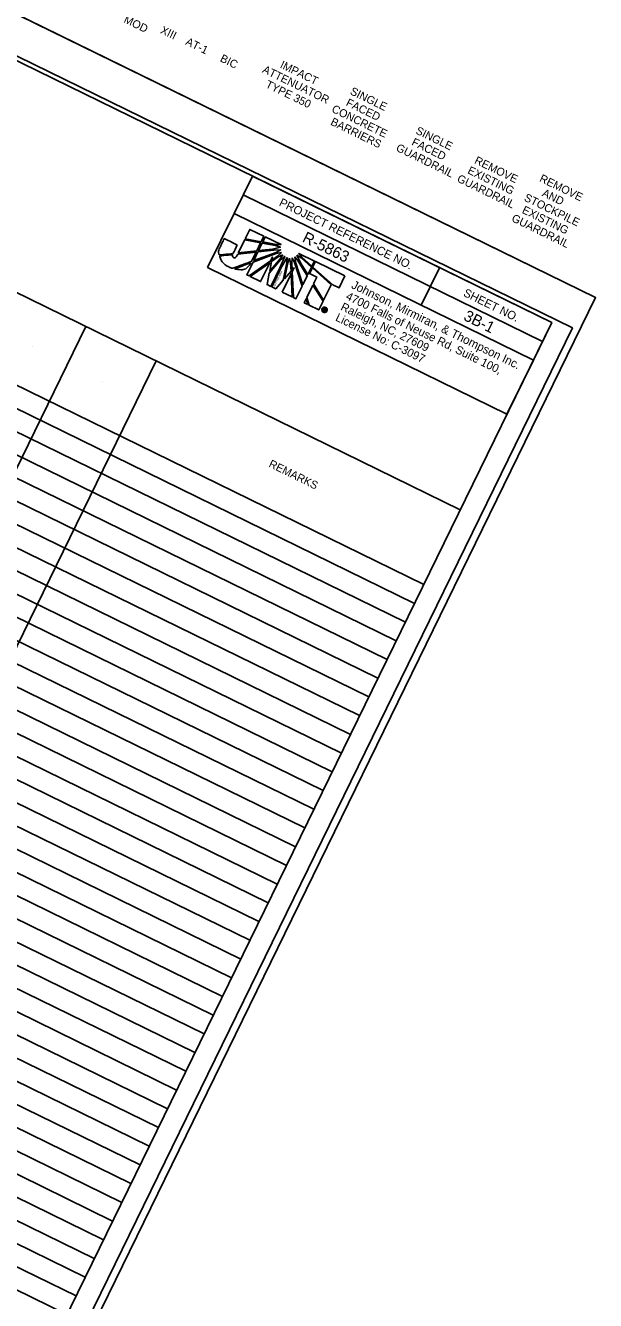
# Model space of a CAD drawing. Extents: x 1524707 to 1527186, y 631886 to 634602.
# Drawn here: x 1526844 to 1527186, y 633261 to 634025 of the extents above; entities that cross this region are included whole.
import ezdxf

# ---------------------------------------------------------------- set-up
doc = ezdxf.new("R2010")
doc.units = 0
for name, color, linetype in [('Sheet Cutting Line CELL', 7, 'Continuous'), ('Sheet Data Field CELL', 7, 'Continuous'), ('Sheet Pipe Summary Grid CELL', 7, 'Continuous'), ('Sheet Plot Border Inside CELL', 7, 'Continuous'), ('Sheet Plot Border Outside CELL', 7, 'Continuous'), ('Sheet Summary Guardrail CELL', 7, 'Continuous')]:
    doc.layers.add(name, color=color, linetype=linetype)

msp = doc.modelspace()

# ---------------------------------------------------------------- linework, layer by layer
at = {"layer": 'Sheet Cutting Line CELL'}
msp.add_line((1527186.47, 633862.17), (1525673.71, 634602.03), dxfattribs=at)
at = {"layer": 'Sheet Pipe Summary Grid CELL'}
for p, q in [((1526978.93, 633903.02), (1526976.21, 633897.44)), ((1526987.35, 633898.92), (1526978.93, 633903.02)), ((1526975.9, 633896.8), (1526972.07, 633888.96)), ((1526985.46, 633895.06), (1526975.9, 633896.8)), ((1526976.21, 633897.44), (1526985.76, 633895.67)), ((1526983.08, 633890.19), (1526985.46, 633895.06)), ((1526986.45, 633894.87), (1526984.23, 633890.32)), ((1526985.76, 633895.67), (1526987.35, 633898.92)), ((1526994.45, 633893.37), (1526986.45, 633894.87)), ((1526988.24, 633898.53), (1526986.77, 633895.52)), ((1526986.77, 633895.52), (1526994.77, 633894.02)), ((1526997.71, 633893.92), (1526988.24, 633898.53)), ((1526972.07, 633888.96), (1526983.08, 633890.19)), ((1526994.82, 633888.6), (1526980.88, 633883.44)), ((1526983.87, 633889.58), (1526981.31, 633884.33)), ((1526981.31, 633884.33), (1526994.69, 633889.24)), ((1526993.42, 633890.66), (1526983.87, 633889.58)), ((1526984.23, 633890.32), (1526992.5, 633891.23)), ((1526992.23, 633884.69), (1526995.56, 633887.04)), ((1526992.5, 633891.23), (1526997.36, 633892.36)), ((1526997.42, 633890.72), (1526993.42, 633890.66)), ((1526997.36, 633892.36), (1526994.45, 633893.37)), ((1526994.69, 633889.24), (1526997.42, 633890.72)), ((1526994.77, 633894.02), (1526997.71, 633893.92)), ((1526997.9, 633889.23), (1526994.82, 633888.6)), ((1526995.56, 633887.04), (1526997.9, 633889.23)), ((1526998.74, 633887.89), (1526996.03, 633886.57)), ((1526997.24, 633885.41), (1526998.74, 633887.89)), ((1527007.28, 633887.53), (1527009.39, 633882.92)), ((1527009.71, 633885.93), (1527007.28, 633887.53)), ((1527017.74, 633884.09), (1527008.43, 633888.69)), ((1527008.43, 633888.69), (1527010.25, 633886.42)), ((1526980.88, 633883.44), (1526977.15, 633875.81)), ((1526978.54, 633875.13), (1526991.47, 633884.2)), ((1526990.89, 633883), (1526979.19, 633874.81)), ((1526985.47, 633871.75), (1526990.89, 633883)), ((1526997.48, 633884.71), (1526990.67, 633876.78)), ((1526990.96, 633878.08), (1526997.24, 633885.41)), ((1526992.08, 633883.79), (1526990.96, 633878.08)), ((1526991.47, 633884.2), (1526992.56, 633886.42)), ((1526991.6, 633868.81), (1526997.07, 633880.03)), ((1526996.03, 633886.57), (1526992.08, 633883.79)), ((1526997.67, 633879.74), (1526992.19, 633868.52)), ((1526992.56, 633886.42), (1526992.23, 633884.69)), ((1526997.07, 633880.03), (1526999.95, 633886.84)), ((1526999.95, 633886.84), (1526997.48, 633884.71)), ((1527001.34, 633886.16), (1526997.67, 633879.74)), ((1526999.04, 633872.52), (1527001.13, 633882.93)), ((1527001.83, 633883.05), (1526999.86, 633873.49)), ((1527001.13, 633882.93), (1527001.34, 633886.16)), ((1527002.86, 633885.88), (1527001.83, 633883.05)), ((1527003.45, 633882.95), (1527002.86, 633885.88)), ((1527003.7, 633877.95), (1527003.45, 633882.95)), ((1527004.42, 633886.05), (1527004.14, 633882.85)), ((1527004.14, 633882.85), (1527004.31, 633878.63)), ((1527004.31, 633878.63), (1527005.55, 633880.08)), ((1527005.55, 633880.08), (1527004.35, 633877.63)), ((1527005.82, 633883.24), (1527004.42, 633886.05)), ((1527010.3, 633868.99), (1527005.82, 633883.24)), ((1527005.9, 633886.58), (1527006.4, 633883.47)), ((1527008.36, 633883.37), (1527005.9, 633886.58)), ((1527006.4, 633883.47), (1527010.72, 633869.86)), ((1527013.35, 633875.25), (1527008.36, 633883.37)), ((1527009.39, 633882.92), (1527013.72, 633876)), ((1527015.95, 633880.43), (1527009.71, 633885.93)), ((1527010.25, 633886.42), (1527016.26, 633881.07)), ((1527013.72, 633876), (1527015.95, 633880.43)), ((1527016.51, 633879.91), (1527014.85, 633876.53)), ((1527016.26, 633881.07), (1527017.74, 633884.09)), ((1527016.53, 633879.97), (1527016.51, 633879.91)), ((1527027.75, 633869.89), (1527016.53, 633879.97)), ((1527016.82, 633880.57), (1527016.78, 633880.47)), ((1527016.78, 633880.47), (1527028.8, 633869.77)), ((1527018.41, 633883.82), (1527016.82, 633880.57)), ((1527036.1, 633875.19), (1527018.41, 633883.82)), ((1526977.15, 633875.81), (1526978.54, 633875.13)), ((1526979.19, 633874.81), (1526985.47, 633871.75)), ((1526990.67, 633876.78), (1526989.29, 633869.94)), ((1526994.53, 633867.38), (1526999.04, 633872.52)), ((1527003.77, 633876.42), (1526998.43, 633865.48)), ((1526999.86, 633873.49), (1527003.7, 633877.95)), ((1527004.45, 633862.54), (1527003.77, 633876.42)), ((1527004.35, 633877.63), (1527005.13, 633862.16)), ((1527010.72, 633869.86), (1527013.35, 633875.25)), ((1527014.85, 633876.53), (1527019.17, 633874.42)), ((1527019.17, 633874.42), (1527017.2, 633870.38)), ((1527032.56, 633867.94), (1527036.1, 633875.19)), ((1526989.29, 633869.94), (1526991.6, 633868.81)), ((1526992.19, 633868.52), (1526994.53, 633867.38)), ((1526998.43, 633865.48), (1527004.45, 633862.54)), ((1527006.61, 633861.43), (1527010.3, 633868.99)), ((1527016.86, 633869.69), (1527013.19, 633862.16)), ((1527022.9, 633859.95), (1527016.86, 633869.69)), ((1527017.2, 633870.38), (1527023.22, 633860.6)), ((1527023.22, 633860.6), (1527027.75, 633869.89)), ((1527028.8, 633869.77), (1527032.56, 633867.94)), ((1527005.13, 633862.16), (1527006.61, 633861.43)), ((1527012.79, 633861.34), (1527011.64, 633858.98)), ((1527011.64, 633858.98), (1527013.82, 633857.92)), ((1527013.82, 633857.92), (1527012.79, 633861.34)), ((1527013.19, 633862.16), (1527014.65, 633857.51)), ((1527014.65, 633857.51), (1527020.36, 633854.73)), ((1527020.36, 633854.73), (1527022.9, 633859.95)), ((1527022.96, 633854.44), (1527023.59, 633855.73)), ((1527023.25, 633854.3), (1527022.96, 633854.44)), ((1527023.24, 633853.68), (1527023.1, 633853.4)), ((1527023.1, 633853.4), (1527023.24, 633853.68)), ((1527023.12, 633853.4), (1527023.1, 633853.4)), ((1527023.24, 633853.68), (1527023.25, 633853.68)), ((1527023.5, 633854.8), (1527023.25, 633854.3)), ((1527023.73, 633854.69), (1527023.5, 633854.8)), ((1527023.59, 633855.73), (1527024.11, 633855.47)), ((1527023.76, 633855.34), (1527023.61, 633855.04)), ((1527023.61, 633855.04), (1527023.84, 633854.92)), ((1527023.84, 633854.92), (1527023.73, 633854.69)), ((1527023.73, 633854.69), (1527023.84, 633854.92)), ((1527023.74, 633854.68), (1527023.73, 633854.69)), ((1527023.99, 633855.23), (1527023.76, 633855.34)), ((1527023.84, 633854.92), (1527023.86, 633854.92)), ((1527024.11, 633855.47), (1527023.99, 633855.23)), ((1527023.99, 633855.23), (1527024.11, 633855.47)), ((1527024.03, 633855.21), (1527023.99, 633855.23)), ((1527024.11, 633855.47), (1527024.19, 633855.43)), ((1527024.48, 633856.23), (1527024.35, 633855.96)), ((1527024.35, 633855.96), (1527024.48, 633856.23))]:
    msp.add_line(p, q, dxfattribs=at)
msp.add_lwpolyline([(1526953.65, 633880.14), (1527133.34, 633792.25), (1527149.2, 633824.68), (1526969.5, 633912.57)], close=True, dxfattribs=at)
for points in [[(1526976.21, 633897.44), (1526985.76, 633895.67), (1526987.35, 633898.92), (1526978.93, 633903.02), (1526976.21, 633897.44)], [(1526972.07, 633888.96), (1526983.08, 633890.19), (1526985.46, 633895.06), (1526975.9, 633896.8), (1526972.07, 633888.96)], [(1526986.45, 633894.87), (1526984.23, 633890.32), (1526992.5, 633891.23), (1526997.36, 633892.36), (1526994.45, 633893.37), (1526986.45, 633894.87)], [(1526994.77, 633894.02), (1526997.71, 633893.92), (1526988.24, 633898.53), (1526986.77, 633895.52), (1526994.77, 633894.02)], [(1526997.9, 633889.23), (1526994.82, 633888.6), (1526980.88, 633883.44), (1526977.15, 633875.81), (1526978.54, 633875.13), (1526991.47, 633884.2), (1526992.56, 633886.42), (1526992.23, 633884.69), (1526995.56, 633887.04), (1526997.9, 633889.23)], [(1526983.87, 633889.58), (1526981.31, 633884.33), (1526994.69, 633889.24), (1526997.42, 633890.72), (1526993.42, 633890.66), (1526983.87, 633889.58)], [(1526998.74, 633887.89), (1526996.03, 633886.57), (1526992.08, 633883.79), (1526990.96, 633878.08), (1526997.24, 633885.41), (1526998.74, 633887.89)], [(1527007.28, 633887.53), (1527009.39, 633882.92), (1527013.72, 633876), (1527015.95, 633880.43), (1527009.71, 633885.93), (1527007.28, 633887.53)], [(1527010.25, 633886.42), (1527016.26, 633881.07), (1527017.74, 633884.09), (1527008.43, 633888.69), (1527010.25, 633886.42)], [(1526979.19, 633874.81), (1526985.47, 633871.75), (1526990.89, 633883), (1526979.19, 633874.81)], [(1526997.48, 633884.71), (1526990.67, 633876.78), (1526989.29, 633869.94), (1526991.6, 633868.81), (1526997.07, 633880.03), (1526999.95, 633886.84), (1526997.48, 633884.71)], [(1527001.34, 633886.16), (1526997.67, 633879.74), (1526992.19, 633868.52), (1526994.53, 633867.38), (1526999.04, 633872.52), (1527001.13, 633882.93), (1527001.34, 633886.16)], [(1527002.86, 633885.88), (1527001.83, 633883.05), (1526999.86, 633873.49), (1527003.7, 633877.95), (1527003.45, 633882.95), (1527002.86, 633885.88)], [(1527004.42, 633886.05), (1527004.14, 633882.85), (1527004.31, 633878.63), (1527005.55, 633880.08), (1527004.35, 633877.63), (1527005.13, 633862.16), (1527006.61, 633861.43), (1527010.3, 633868.99), (1527005.82, 633883.24), (1527004.42, 633886.05)], [(1527005.9, 633886.58), (1527006.4, 633883.47), (1527010.72, 633869.86), (1527013.35, 633875.25), (1527008.36, 633883.37), (1527005.9, 633886.58)], [(1527016.53, 633879.97), (1527016.51, 633879.91), (1527014.85, 633876.53), (1527019.17, 633874.42), (1527017.2, 633870.38), (1527023.22, 633860.6), (1527027.75, 633869.89), (1527016.53, 633879.97)], [(1527036.1, 633875.19), (1527018.41, 633883.82), (1527016.82, 633880.57), (1527016.78, 633880.47), (1527028.8, 633869.77), (1527032.56, 633867.94), (1527036.1, 633875.19)], [(1526998.43, 633865.48), (1527004.45, 633862.54), (1527003.77, 633876.42), (1526998.43, 633865.48)], [(1527016.86, 633869.69), (1527013.19, 633862.16), (1527014.65, 633857.51), (1527020.36, 633854.73), (1527022.9, 633859.95), (1527016.86, 633869.69), (1527016.86, 633869.69)], [(1527011.64, 633858.98), (1527011.64, 633858.98), (1527013.82, 633857.92), (1527012.79, 633861.34), (1527011.64, 633858.98)], [(1527024.2, 633854.21), (1527024.16, 633854.14), (1527024.15, 633854.09), (1527024.13, 633854.05), (1527024.09, 633853.89), (1527023.82, 633854.02)]]:
    msp.add_lwpolyline(points, dxfattribs=at)
for points, degree in [([(1526971.42, 633893.75), (1526971.42, 633893.75), (1526963.63, 633897.55), (1526963.63, 633897.55), (1526963.63, 633897.55), (1526961.25, 633892.68), (1526961.25, 633892.68), (1526961.25, 633892.68), (1526961, 633892.16), (1526961, 633892.16), (1526960.25, 633890.64), (1526960.16, 633889.18), (1526960.56, 633887.74), (1526960.56, 633887.74), (1526968.86, 633888.5), (1526968.9, 633888.6), (1526968.9, 633888.6), (1526971.42, 633893.75), (1526971.42, 633893.75)], 3), ([(1526969.2, 633886.15), (1526968.7, 633886.39), (1526968.41, 633886.88), (1526968.68, 633887.9), (1526968.68, 633887.9), (1526960.82, 633887.11), (1526960.82, 633887.11), (1526961.73, 633884.25), (1526964.13, 633881.63), (1526966.64, 633880.4), (1526967.29, 633880.09), (1526967.82, 633879.9), (1526968.58, 633879.7), (1526968.58, 633879.7), (1526979.98, 633883.83), (1526979.98, 633883.83), (1526979.98, 633883.83), (1526982.75, 633889.49), (1526982.75, 633889.49), (1526982.75, 633889.49), (1526971.72, 633888.25), (1526971.72, 633888.25), (1526970.69, 633886.13), (1526969.9, 633885.81), (1526969.2, 633886.15)], 3), ([(1526969.2, 633886.15), (1526968.7, 633886.39), (1526968.41, 633886.88), (1526968.68, 633887.9), (1526968.68, 633887.9), (1526960.82, 633887.11), (1526960.82, 633887.11), (1526961.73, 633884.25), (1526964.13, 633881.63), (1526966.64, 633880.4), (1526967.29, 633880.09), (1526967.82, 633879.9), (1526968.58, 633879.7), (1526968.58, 633879.7), (1526979.98, 633883.83), (1526979.98, 633883.83), (1526979.98, 633883.83), (1526982.75, 633889.49), (1526982.75, 633889.49), (1526982.75, 633889.49), (1526971.72, 633888.25), (1526971.72, 633888.25), (1526970.69, 633886.13), (1526969.9, 633885.81), (1526969.2, 633886.15)], 3), ([(1526979.55, 633882.94), (1526979.55, 633882.94), (1526969.7, 633879.38), (1526969.7, 633879.38), (1526973.29, 633878.6), (1526977.52, 633879.17), (1526979.55, 633882.94)], 3), ([(1527023.1, 633853.4), (1527022.72, 633853.59), (1527022.45, 633853.9), (1527022.3, 633854.31), (1527022.15, 633854.72), (1527022.18, 633855.13), (1527022.37, 633855.52), (1527022.57, 633855.92), (1527022.87, 633856.19), (1527023.28, 633856.31), (1527023.69, 633856.44), (1527024.09, 633856.43), (1527024.48, 633856.23)], 3), ([(1527024.35, 633855.96), (1527024.04, 633856.12), (1527023.72, 633856.14), (1527023.39, 633856.04), (1527023.06, 633855.93), (1527022.81, 633855.7), (1527022.65, 633855.39), (1527022.5, 633855.07), (1527022.48, 633854.73), (1527022.59, 633854.4), (1527022.71, 633854.07), (1527022.92, 633853.84), (1527023.24, 633853.68)], 3), ([(1527025.24, 633854.13), (1527025.04, 633853.73), (1527024.74, 633853.46), (1527024.33, 633853.31), (1527023.92, 633853.18), (1527023.51, 633853.2), (1527023.12, 633853.4)], 3), ([(1527023.25, 633853.68), (1527023.57, 633853.52), (1527023.89, 633853.5), (1527024.22, 633853.61), (1527024.55, 633853.72), (1527024.8, 633853.95), (1527024.96, 633854.26), (1527025.11, 633854.58), (1527025.13, 633854.92), (1527025.02, 633855.25), (1527024.9, 633855.57), (1527024.68, 633855.8), (1527024.35, 633855.96)], 3), ([(1527023.94, 633854.53), (1527023.92, 633854.57), (1527023.86, 633854.62), (1527023.74, 633854.68)], 2), ([(1527023.82, 633854.02), (1527023.82, 633854.11), (1527023.83, 633854.19), (1527023.88, 633854.28), (1527023.94, 633854.4), (1527023.96, 633854.47), (1527023.94, 633854.53)], 3), ([(1527023.86, 633854.92), (1527024.04, 633854.82), (1527024.17, 633854.84), (1527024.22, 633854.94), (1527024.26, 633855.04), (1527024.2, 633855.12), (1527024.03, 633855.21)], 3), ([(1527024.19, 633855.43), (1527024.52, 633855.27), (1527024.62, 633855.06), (1527024.5, 633854.81), (1527024.44, 633854.69), (1527024.35, 633854.62), (1527024.21, 633854.6)], 3), ([(1527024.21, 633854.6), (1527024.27, 633854.51), (1527024.26, 633854.38), (1527024.2, 633854.21)], 2), ([(1527024.48, 633856.23), (1527024.88, 633856.04), (1527025.15, 633855.73), (1527025.3, 633855.33), (1527025.46, 633854.93), (1527025.43, 633854.52), (1527025.24, 633854.13)], 3)]:
    msp.add_open_spline(points, degree=degree, dxfattribs=at)
at = {"layer": 'Sheet Plot Border Inside CELL'}
msp.add_lwpolyline([(1525211.97, 633628.34), (1526709.01, 632896.16), (1527172.57, 633843.98), (1525675.52, 634576.15)], close=True, dxfattribs=at)
at = {"layer": 'Sheet Plot Border Outside CELL'}
msp.add_lwpolyline([(1525190.43, 633613.88), (1526703.19, 632874.02), (1527186.47, 633862.17), (1525673.71, 634602.03)], close=True, dxfattribs=at)
at = {"layer": 'Sheet Summary Guardrail CELL'}
for p, q in [((1525757.82, 634393.91), (1527105.3, 633734.89)), ((1525735.86, 634348.99), (1527083.33, 633689.97)), ((1525730.37, 634337.76), (1527077.84, 633678.74)), ((1525724.87, 634326.54), (1527072.35, 633667.51)), ((1525719.38, 634315.31), (1527066.86, 633656.29)), ((1525713.89, 634304.08), (1527061.37, 633645.06)), ((1525708.4, 634292.85), (1527055.87, 633633.83)), ((1525702.91, 634281.62), (1527050.38, 633622.6)), ((1525697.41, 634270.39), (1527044.89, 633611.37)), ((1525691.92, 634259.16), (1527039.4, 633600.14)), ((1525686.43, 634247.93), (1527033.91, 633588.91)), ((1525680.94, 634236.7), (1527028.41, 633577.68)), ((1525675.45, 634225.48), (1527022.92, 633566.45)), ((1525669.96, 634214.25), (1527017.43, 633555.22)), ((1525664.46, 634203.02), (1527011.94, 633544)), ((1525658.97, 634191.79), (1527006.45, 633532.77)), ((1525653.48, 634180.56), (1527000.96, 633521.54)), ((1525647.99, 634169.33), (1526995.46, 633510.31)), ((1525642.5, 634158.1), (1526989.97, 633499.08)), ((1525637, 634146.87), (1526984.48, 633487.85)), ((1525631.51, 634135.64), (1526978.99, 633476.62)), ((1525626.02, 634124.41), (1526973.5, 633465.39)), ((1525620.53, 634113.19), (1526968, 633454.16)), ((1525615.04, 634101.96), (1526962.51, 633442.93)), ((1525609.54, 634090.73), (1526957.02, 633431.71)), ((1525604.05, 634079.5), (1526951.53, 633420.48)), ((1525598.56, 634068.27), (1526946.04, 633409.25)), ((1525593.07, 634057.04), (1526940.54, 633398.02)), ((1525587.58, 634045.81), (1526935.05, 633386.79)), ((1525582.09, 634034.58), (1526929.56, 633375.56)), ((1525576.59, 634023.35), (1526924.07, 633364.33)), ((1525571.1, 634012.12), (1526918.58, 633353.1)), ((1525565.61, 634000.9), (1526913.09, 633341.87)), ((1525560.12, 633989.67), (1526907.59, 633330.65)), ((1525554.63, 633978.44), (1526902.1, 633319.42)), ((1525549.13, 633967.21), (1526896.61, 633308.19)), ((1525543.64, 633955.98), (1526891.12, 633296.96)), ((1525538.15, 633944.75), (1526885.63, 633285.73)), ((1525532.66, 633933.52), (1526880.13, 633274.5)), ((1525527.17, 633922.29), (1526874.64, 633263.27)), ((1526975, 633923.8), (1527154.71, 633835.9)), ((1525521.68, 633911.06), (1526869.15, 633252.04)), ((1527092.82, 633880.08), (1527081.84, 633857.63)), ((1526880.63, 633844.77), (1526474.23, 633013.83)), ((1526848.54, 633832.64), (1526848.54, 633832.64)), ((1526922.85, 633824.12), (1526516.46, 632993.18)), ((1526890.76, 633811.99), (1526890.76, 633811.99))]:
    msp.add_line(p, q, dxfattribs=at)
for points in [[(1527160.22, 633847.18), (1525812.74, 634506.2), (1525351.43, 633562.97), (1526698.9, 632903.94)], [(1526980.51, 633935.07), (1527160.22, 633847.18), (1527149.21, 633824.67), (1526969.5, 633912.57)]]:
    msp.add_lwpolyline(points, close=True, dxfattribs=at)

# ---------------------------------------------------------------- texts
at = {"layer": 'Sheet Data Field CELL'}
for s, p in [('R-5863', (1527009.99, 633895.94)), ('3B-1', (1527106.77, 633848.94))]:
    msp.add_text(s, height=6.75, rotation=333.93772, dxfattribs=at).set_placement(p)
at = {"layer": 'Sheet Pipe Summary Grid CELL'}
for s, height, rotation, p in [('www.jmt.com', 1.2413, 243.93772, (1526997.67, 633878.32)), ('Johnson, Mirmiran, & Thompson Inc.', 5.1112, 333.93772, (1527039.45, 633868.07)), ('4700 Falls of Neuse Rd, Suite 100, ', 4.9652, 333.93772, (1527036.15, 633861.33)), ('Raleigh, NC, 27609', 4.9652, 333.93772, (1527033.03, 633854.96)), ('License No: C-3097', 4.9652, 333.93772, (1527029.92, 633848.58))]:
    msp.add_text(s, height=height, rotation=rotation, dxfattribs=at).set_placement(p)
at = {"layer": 'Sheet Summary Guardrail CELL'}
for s, height, p in [('MOD', 4.8, (1526902.89, 634027.41)), ('XIII', 4.8, (1526924.86, 634021.01)), ('AT-1', 4.8, (1526939.97, 634014.12)), ('BIC', 4.8, (1526960.7, 634004.04)), ('IMPACT', 4.8, (1526996.69, 634000.24)), ('ATTENUATOR', 4.8, (1526986.11, 633997.39)), ('TYPE 350', 4.8, (1526987.98, 633988.47)), ('SINGLE', 4.8, (1527038.73, 633984.35)), ('FACED', 4.8, (1527036.29, 633977.53)), ('CONCRETE', 4.8, (1527027.64, 633973.74)), ('BARRIERS', 4.8, (1527027, 633966.05)), ('SINGLE', 4.8, (1527078.09, 633960.7)), ('FACED', 4.8, (1527075.65, 633953.88)), ('GUARDRAIL', 4.8, (1527066.29, 633950.45)), ('EXISTING', 4.8, (1527109.25, 633936.89)), ('REMOVE', 4.8, (1527113.4, 633942.88)), ('GUARDRAIL', 4.8, (1527102.94, 633931.96)), ('REMOVE', 4.8, (1527152.41, 633932.04)), ('AND', 4.8, (1527153.92, 633923.29)), ('PROJECT REFERENCE NO.', 5.0001, (1526996.09, 633917.54)), ('STOCKPILE', 4.8, (1527143.16, 633920.53)), ('GUARDRAIL', 4.8, (1527135.62, 633908.19)), ('EXISTING', 4.8, (1527141.93, 633913.12)), ('SHEET NO.', 5, (1527106.68, 633863.34)), ('REMARKS', 4.8, (1526989.91, 633760.82))]:
    msp.add_text(s, height=height, rotation=333.93772, dxfattribs=at).set_placement(p)

doc.saveas('drawing.dxf')
